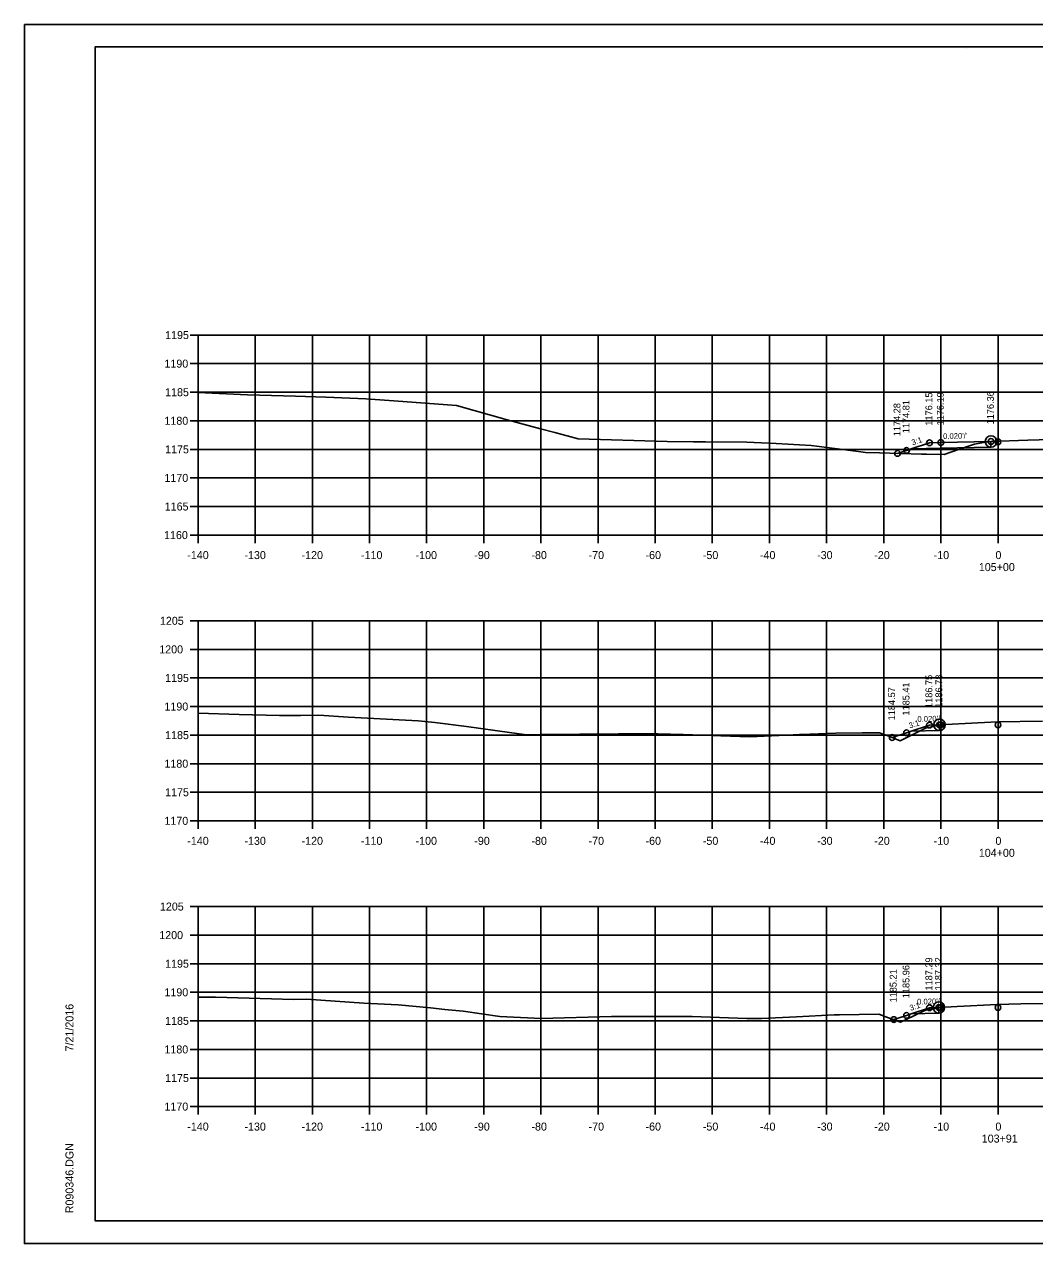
# Model space of a CAD drawing. Extents: x 1368971 to 1374497, y 378717 to 381839.
# Drawn here: x 1371092.2 to 1371269, y 380772.8 to 380986.1 of the extents above; entities that cross this region are included whole.
import ezdxf

# ---------------------------------------------------------------- set-up
doc = ezdxf.new("R2010")
doc.units = 0
for name, color, linetype in [('R_Alt Surface', 7, 'Continuous'), ('R_Axis', 7, 'Continuous'), ('R_Axis Annot', 7, 'Continuous'), ('R_Exist Surface', 7, 'Continuous'), ('R_Fin Surface', 7, 'Continuous'), ('R_Grid', 7, 'Continuous'), ('R_No Plot', 7, 'Continuous'), ('R_Xsect Elev', 7, 'Continuous'), ('R_Xsect Slope', 7, 'Continuous')]:
    doc.layers.add(name, color=color, linetype=linetype)

msp = doc.modelspace()

# ---------------------------------------------------------------- linework, layer by layer
at = {"layer": 'R_Alt Surface'}
for points in [[(1371261.41, 380913.1), (1371261.41, 380912.1), (1371252.64, 380911.92), (1371247.45, 380911.82)], [(1371252.39, 380863.52), (1371252.39, 380862.52), (1371247.45, 380862.42)], [(1371252.3, 380814.06), (1371252.3, 380813.06), (1371247.45, 380812.96)]]:
    msp.add_lwpolyline(points, dxfattribs=at)
at = {"layer": 'R_Axis'}
for p, q in [((1371121.24, 380931.73), (1371122.64, 380931.73)), ((1371122.64, 380896.73), (1371122.64, 380931.73)), ((1371121.24, 380926.73), (1371122.64, 380926.73)), ((1371121.24, 380921.73), (1371122.64, 380921.73)), ((1371121.24, 380916.73), (1371122.64, 380916.73)), ((1371121.24, 380911.73), (1371122.64, 380911.73)), ((1371121.24, 380906.73), (1371122.64, 380906.73)), ((1371121.24, 380901.73), (1371122.64, 380901.73)), ((1371121.24, 380896.73), (1371122.64, 380896.73)), ((1371122.64, 380896.73), (1371402.64, 380896.73)), ((1371122.64, 380895.33), (1371122.64, 380896.73)), ((1371132.64, 380895.33), (1371132.64, 380896.73)), ((1371142.64, 380895.33), (1371142.64, 380896.73)), ((1371152.64, 380895.33), (1371152.64, 380896.73)), ((1371162.64, 380895.33), (1371162.64, 380896.73)), ((1371172.64, 380895.33), (1371172.64, 380896.73)), ((1371182.64, 380895.33), (1371182.64, 380896.73)), ((1371192.64, 380895.33), (1371192.64, 380896.73)), ((1371202.64, 380895.33), (1371202.64, 380896.73)), ((1371212.64, 380895.33), (1371212.64, 380896.73)), ((1371222.64, 380895.33), (1371222.64, 380896.73)), ((1371232.64, 380895.33), (1371232.64, 380896.73)), ((1371242.64, 380895.33), (1371242.64, 380896.73)), ((1371252.64, 380895.33), (1371252.64, 380896.73)), ((1371262.64, 380895.33), (1371262.64, 380896.73)), ((1371121.24, 380881.73), (1371122.64, 380881.73)), ((1371122.64, 380846.73), (1371122.64, 380881.73)), ((1371121.24, 380876.73), (1371122.64, 380876.73)), ((1371121.24, 380871.73), (1371122.64, 380871.73)), ((1371121.24, 380866.73), (1371122.64, 380866.73)), ((1371121.24, 380861.73), (1371122.64, 380861.73)), ((1371121.24, 380856.73), (1371122.64, 380856.73)), ((1371121.24, 380851.73), (1371122.64, 380851.73)), ((1371121.24, 380846.73), (1371122.64, 380846.73)), ((1371122.64, 380846.73), (1371402.64, 380846.73)), ((1371122.64, 380845.33), (1371122.64, 380846.73)), ((1371132.64, 380845.33), (1371132.64, 380846.73)), ((1371142.64, 380845.33), (1371142.64, 380846.73)), ((1371152.64, 380845.33), (1371152.64, 380846.73)), ((1371162.64, 380845.33), (1371162.64, 380846.73)), ((1371172.64, 380845.33), (1371172.64, 380846.73)), ((1371182.64, 380845.33), (1371182.64, 380846.73)), ((1371192.64, 380845.33), (1371192.64, 380846.73)), ((1371202.64, 380845.33), (1371202.64, 380846.73)), ((1371212.64, 380845.33), (1371212.64, 380846.73)), ((1371222.64, 380845.33), (1371222.64, 380846.73)), ((1371232.64, 380845.33), (1371232.64, 380846.73)), ((1371242.64, 380845.33), (1371242.64, 380846.73)), ((1371252.64, 380845.33), (1371252.64, 380846.73)), ((1371262.64, 380845.33), (1371262.64, 380846.73)), ((1371121.24, 380831.73), (1371122.64, 380831.73)), ((1371122.64, 380796.73), (1371122.64, 380831.73)), ((1371121.24, 380826.73), (1371122.64, 380826.73)), ((1371121.24, 380821.73), (1371122.64, 380821.73)), ((1371121.24, 380816.73), (1371122.64, 380816.73)), ((1371121.24, 380811.73), (1371122.64, 380811.73)), ((1371121.24, 380806.73), (1371122.64, 380806.73)), ((1371121.24, 380801.73), (1371122.64, 380801.73)), ((1371121.24, 380796.73), (1371122.64, 380796.73)), ((1371122.64, 380796.73), (1371402.64, 380796.73)), ((1371122.64, 380795.33), (1371122.64, 380796.73)), ((1371132.64, 380795.33), (1371132.64, 380796.73)), ((1371142.64, 380795.33), (1371142.64, 380796.73)), ((1371152.64, 380795.33), (1371152.64, 380796.73)), ((1371162.64, 380795.33), (1371162.64, 380796.73)), ((1371172.64, 380795.33), (1371172.64, 380796.73)), ((1371182.64, 380795.33), (1371182.64, 380796.73)), ((1371192.64, 380795.33), (1371192.64, 380796.73)), ((1371202.64, 380795.33), (1371202.64, 380796.73)), ((1371212.64, 380795.33), (1371212.64, 380796.73)), ((1371222.64, 380795.33), (1371222.64, 380796.73)), ((1371232.64, 380795.33), (1371232.64, 380796.73)), ((1371242.64, 380795.33), (1371242.64, 380796.73)), ((1371252.64, 380795.33), (1371252.64, 380796.73)), ((1371262.64, 380795.33), (1371262.64, 380796.73))]:
    msp.add_line(p, q, dxfattribs=at)
at = {"layer": 'R_Exist Surface'}
for points in [[(1371122.64, 380921.69), (1371131.3, 380921.28), (1371139.66, 380921.01), (1371145.02, 380920.88), (1371152.02, 380920.59), (1371156.92, 380920.2), (1371167.89, 380919.41), (1371176.72, 380916.9), (1371182.58, 380915.31), (1371185.08, 380914.68), (1371189.17, 380913.59), (1371204.71, 380913.09), (1371209.36, 380913.02), (1371211.44, 380913.04), (1371218.7, 380912.97), (1371223.8, 380912.74), (1371229.91, 380912.38), (1371238.24, 380911.34), (1371239.46, 380911.17), (1371241.87, 380911.1), (1371249.23, 380910.91), (1371250.15, 380910.87), (1371253.22, 380910.81), (1371255.73, 380911.72), (1371258.5, 380912.62), (1371260.09, 380912.91), (1371261.41, 380913.1), (1371267.83, 380913.34), (1371271.83, 380913.48)], [(1371122.64, 380865.56), (1371129.84, 380865.35), (1371136.91, 380865.14), (1371140.56, 380865.14), (1371143.77, 380865.2), (1371148.96, 380864.85), (1371161.16, 380864.25), (1371164.1, 380863.95), (1371169.6, 380863.25), (1371177.16, 380862.19), (1371179.68, 380861.84), (1371180.8, 380861.78), (1371182.65, 380861.84), (1371196.24, 380861.93), (1371203.11, 380861.93), (1371207.52, 380861.85), (1371217.45, 380861.48), (1371219.21, 380861.42), (1371226.8, 380861.78), (1371227.88, 380861.83), (1371228.17, 380861.85), (1371234.27, 380862.07), (1371238.86, 380862.1), (1371241.9, 380862.14), (1371243.71, 380861.47), (1371245.53, 380860.75), (1371248.9, 380862.42), (1371249.96, 380862.93), (1371250.75, 380863.1), (1371252.39, 380863.52), (1371259.08, 380863.88), (1371262.54, 380864.06), (1371270.4, 380864.17)], [(1371122.64, 380815.89), (1371125.7, 380815.86), (1371135.46, 380815.57), (1371139.26, 380815.49), (1371141.6, 380815.53), (1371151.66, 380814.85), (1371157.65, 380814.56), (1371163.29, 380813.98), (1371165.82, 380813.72), (1371169.05, 380813.4), (1371175.42, 380812.51), (1371182.69, 380812.13), (1371195.02, 380812.52), (1371195.1, 380812.52), (1371195.24, 380812.52), (1371206.59, 380812.48), (1371209.13, 380812.5), (1371218.7, 380812.14), (1371221.23, 380812.16), (1371227.39, 380812.43), (1371233.96, 380812.79), (1371234.48, 380812.81), (1371234.87, 380812.81), (1371241.8, 380812.91), (1371243.95, 380812.11), (1371245.57, 380811.52), (1371246.42, 380811.91), (1371249.84, 380813.56), (1371251.34, 380813.89), (1371252.3, 380814.06), (1371255.48, 380814.24), (1371262.41, 380814.62), (1371266.62, 380814.68), (1371273.43, 380814.78)]]:
    msp.add_lwpolyline(points, dxfattribs=at)
at = {"layer": 'R_Fin Surface'}
for points in [[(1371245.06, 380911.02), (1371246.64, 380911.55), (1371247.45, 380911.82), (1371250.64, 380912.88), (1371252.64, 380912.92), (1371261.41, 380913.1)], [(1371244.12, 380861.31), (1371246.64, 380862.15), (1371247.45, 380862.42), (1371250.64, 380863.48), (1371252.39, 380863.52)], [(1371244.4, 380811.95), (1371246.64, 380812.69), (1371246.64, 380812.69), (1371246.65, 380812.69), (1371247.45, 380812.96), (1371247.46, 380812.97), (1371250.64, 380814.03), (1371250.65, 380814.03), (1371252.3, 380814.06), (1371252.3, 380814.06)]]:
    msp.add_lwpolyline(points, dxfattribs=at)
at = {"layer": 'R_Grid'}
for p, q in [((1371122.64, 380931.73), (1371402.64, 380931.73)), ((1371122.64, 380896.73), (1371122.64, 380931.73)), ((1371132.64, 380896.73), (1371132.64, 380931.73)), ((1371142.64, 380896.73), (1371142.64, 380931.73)), ((1371152.64, 380896.73), (1371152.64, 380931.73)), ((1371162.64, 380896.73), (1371162.64, 380931.73)), ((1371172.64, 380896.73), (1371172.64, 380931.73)), ((1371182.64, 380896.73), (1371182.64, 380931.73)), ((1371192.64, 380896.73), (1371192.64, 380931.73)), ((1371202.64, 380896.73), (1371202.64, 380931.73)), ((1371212.64, 380896.73), (1371212.64, 380931.73)), ((1371222.64, 380896.73), (1371222.64, 380931.73)), ((1371232.64, 380896.73), (1371232.64, 380931.73)), ((1371242.64, 380896.73), (1371242.64, 380931.73)), ((1371252.64, 380896.73), (1371252.64, 380931.73)), ((1371262.64, 380896.73), (1371262.64, 380931.73)), ((1371122.64, 380926.73), (1371402.64, 380926.73)), ((1371122.64, 380921.73), (1371402.64, 380921.73)), ((1371122.64, 380916.73), (1371402.64, 380916.73)), ((1371122.64, 380911.73), (1371402.64, 380911.73)), ((1371122.64, 380906.73), (1371402.64, 380906.73)), ((1371122.64, 380901.73), (1371402.64, 380901.73)), ((1371122.64, 380896.73), (1371402.64, 380896.73)), ((1371122.64, 380881.73), (1371402.64, 380881.73)), ((1371122.64, 380846.73), (1371122.64, 380881.73)), ((1371132.64, 380846.73), (1371132.64, 380881.73)), ((1371142.64, 380846.73), (1371142.64, 380881.73)), ((1371152.64, 380846.73), (1371152.64, 380881.73)), ((1371162.64, 380846.73), (1371162.64, 380881.73)), ((1371172.64, 380846.73), (1371172.64, 380881.73)), ((1371182.64, 380846.73), (1371182.64, 380881.73)), ((1371192.64, 380846.73), (1371192.64, 380881.73)), ((1371202.64, 380846.73), (1371202.64, 380881.73)), ((1371212.64, 380846.73), (1371212.64, 380881.73)), ((1371222.64, 380846.73), (1371222.64, 380881.73)), ((1371232.64, 380846.73), (1371232.64, 380881.73)), ((1371242.64, 380846.73), (1371242.64, 380881.73)), ((1371252.64, 380846.73), (1371252.64, 380881.73)), ((1371262.64, 380846.73), (1371262.64, 380881.73)), ((1371122.64, 380876.73), (1371402.64, 380876.73)), ((1371122.64, 380871.73), (1371402.64, 380871.73)), ((1371122.64, 380866.73), (1371402.64, 380866.73)), ((1371122.64, 380861.73), (1371402.64, 380861.73)), ((1371122.64, 380856.73), (1371402.64, 380856.73)), ((1371122.64, 380851.73), (1371402.64, 380851.73)), ((1371122.64, 380846.73), (1371402.64, 380846.73)), ((1371122.64, 380831.73), (1371402.64, 380831.73)), ((1371122.64, 380796.73), (1371122.64, 380831.73)), ((1371132.64, 380796.73), (1371132.64, 380831.73)), ((1371142.64, 380796.73), (1371142.64, 380831.73)), ((1371152.64, 380796.73), (1371152.64, 380831.73)), ((1371162.64, 380796.73), (1371162.64, 380831.73)), ((1371172.64, 380796.73), (1371172.64, 380831.73)), ((1371182.64, 380796.73), (1371182.64, 380831.73)), ((1371192.64, 380796.73), (1371192.64, 380831.73)), ((1371202.64, 380796.73), (1371202.64, 380831.73)), ((1371212.64, 380796.73), (1371212.64, 380831.73)), ((1371222.64, 380796.73), (1371222.64, 380831.73)), ((1371232.64, 380796.73), (1371232.64, 380831.73)), ((1371242.64, 380796.73), (1371242.64, 380831.73)), ((1371252.64, 380796.73), (1371252.64, 380831.73)), ((1371262.64, 380796.73), (1371262.64, 380831.73)), ((1371122.64, 380826.73), (1371402.64, 380826.73)), ((1371122.64, 380821.73), (1371402.64, 380821.73)), ((1371122.64, 380816.73), (1371402.64, 380816.73)), ((1371122.64, 380811.73), (1371402.64, 380811.73)), ((1371122.64, 380806.73), (1371402.64, 380806.73)), ((1371122.64, 380801.73), (1371402.64, 380801.73)), ((1371122.64, 380796.73), (1371402.64, 380796.73))]:
    msp.add_line(p, q, dxfattribs=at)
at = {"layer": 'R_No Plot'}
for p, q in [((1371092.24, 380986.09), (1371425.58, 380986.09)), ((1371104.64, 380982.19), (1371420.82, 380982.19)), ((1371104.64, 380776.73), (1371104.64, 380982.19)), ((1371257.16, 380981.93), (1371257.16, 380981.93)), ((1371257.16, 380981.93), (1371257.16, 380981.93)), ((1371104.64, 380776.73), (1371104.64, 380776.73)), ((1371420.82, 380776.73), (1371104.64, 380776.73)), ((1371092.24, 380772.76), (1371425.58, 380772.76))]:
    msp.add_line(p, q, dxfattribs=at)
for points in [[(1371092.24, 380986.09), (1371425.58, 380986.09), (1371425.58, 380772.75), (1371092.24, 380772.75)], [(1371338.56, 380982.19), (1371338.56, 380972.31), (1371374.3, 380972.31), (1371374.3, 380969.39), (1371397.49, 380969.39), (1371397.49, 380946.18), (1371420.82, 380946.18), (1371420.82, 380776.73), (1371104.64, 380776.73), (1371104.64, 380982.19)]]:
    msp.add_lwpolyline(points, close=True, dxfattribs=at)
for centre, radius in [((1371250.64, 380912.88), 0.5), ((1371252.64, 380912.92), 0.5), ((1371261.41, 380913.1), 1), ((1371261.41, 380913.1), 0.5), ((1371262.64, 380913.04), 0.5), ((1371245.06, 380911.02), 0.5), ((1371246.64, 380911.55), 0.5), ((1371250.64, 380863.48), 0.5), ((1371252.39, 380863.52), 1), ((1371252.39, 380863.52), 0.5), ((1371252.64, 380863.52), 0.5), ((1371262.64, 380863.52), 0.5), ((1371244.12, 380861.31), 0.5), ((1371246.64, 380862.15), 0.5), ((1371250.64, 380814.03), 0.5), ((1371252.3, 380814.06), 1), ((1371252.3, 380814.06), 0.5), ((1371252.64, 380814.07), 0.5), ((1371262.64, 380814.07), 0.5), ((1371244.4, 380811.95), 0.5), ((1371246.64, 380812.69), 0.5)]:
    msp.add_circle(centre, radius, dxfattribs=at)

# ---------------------------------------------------------------- texts
at = {"layer": 'R_Axis'}
for p in [(1371122.64, 380896.73), (1371122.64, 380846.73), (1371122.64, 380796.73)]:
    msp.add_text('-', height=0.0001, dxfattribs=at).set_placement(p)
at = {"layer": 'R_Axis Annot'}
for s, p in [('1195', (1371116.87, 380931.03)), ('1190', (1371116.75, 380926.03)), ('1185', (1371116.87, 380921.03)), ('1180', (1371116.75, 380916.03)), ('1175', (1371116.87, 380911.03)), ('1170', (1371116.75, 380906.03)), ('1165', (1371116.8, 380901.03)), ('1160', (1371116.68, 380896.03)), ('-140', (1371120.75, 380892.53)), ('-130', (1371130.75, 380892.53)), ('-120', (1371140.75, 380892.53)), ('-110', (1371151.15, 380892.53)), ('-100', (1371160.7, 380892.53)), ('-90', (1371170.98, 380892.53)), ('-80', (1371180.98, 380892.53)), ('-70', (1371190.98, 380892.53)), ('-60', (1371200.95, 380892.53)), ('-50', (1371210.98, 380892.53)), ('-40', (1371220.98, 380892.53)), ('-30', (1371230.98, 380892.53)), ('-20', (1371240.98, 380892.53)), ('-10', (1371251.38, 380892.53)), ('0', (1371262.19, 380892.53)), ('105+00', (1371259.28, 380890.43)), ('1205', (1371115.96, 380881.03)), ('1200', (1371115.84, 380876.03)), ('1195', (1371116.87, 380871.03)), ('1190', (1371116.75, 380866.03)), ('1185', (1371116.87, 380861.03)), ('1180', (1371116.75, 380856.03)), ('1175', (1371116.87, 380851.03)), ('1170', (1371116.75, 380846.03)), ('-140', (1371120.75, 380842.53)), ('-130', (1371130.75, 380842.53)), ('-120', (1371140.75, 380842.53)), ('-110', (1371151.15, 380842.53)), ('-100', (1371160.7, 380842.53)), ('-90', (1371170.98, 380842.53)), ('-80', (1371180.98, 380842.53)), ('-70', (1371190.98, 380842.53)), ('-60', (1371200.95, 380842.53)), ('-50', (1371210.98, 380842.53)), ('-40', (1371220.98, 380842.53)), ('-30', (1371230.98, 380842.53)), ('-20', (1371240.98, 380842.53)), ('-10', (1371251.38, 380842.53)), ('0', (1371262.19, 380842.53)), ('104+00', (1371259.28, 380840.43)), ('1205', (1371115.96, 380831.03)), ('1200', (1371115.84, 380826.03)), ('1195', (1371116.87, 380821.03)), ('1190', (1371116.75, 380816.03)), ('1185', (1371116.87, 380811.03)), ('1180', (1371116.75, 380806.03)), ('1175', (1371116.87, 380801.03)), ('1170', (1371116.75, 380796.03)), ('-140', (1371120.75, 380792.53)), ('-130', (1371130.75, 380792.53)), ('-120', (1371140.75, 380792.53)), ('-110', (1371151.15, 380792.53)), ('-100', (1371160.7, 380792.53)), ('-90', (1371170.98, 380792.53)), ('-80', (1371180.98, 380792.53)), ('-70', (1371190.98, 380792.53)), ('-60', (1371200.95, 380792.53)), ('-50', (1371210.98, 380792.53)), ('-40', (1371220.98, 380792.53)), ('-30', (1371230.98, 380792.53)), ('-20', (1371240.98, 380792.53)), ('-10', (1371251.38, 380792.53)), ('0', (1371262.19, 380792.53)), ('103+91', (1371259.79, 380790.43))]:
    msp.add_text(s, height=1.4, dxfattribs=at).set_placement(p)
at = {"layer": 'R_No Plot'}
for s, p in [('7/21/2016', (1371100.83, 380806.38)), ('R090346.DGN', (1371100.83, 380778.06))]:
    msp.add_text(s, height=1.4, rotation=90, dxfattribs=at).set_placement(p)
at = {"layer": 'R_Xsect Elev'}
for s, p in [('1176.15', (1371251.14, 380915.88)), ('1176.19', (1371253.14, 380915.92)), ('1176.36', (1371261.91, 380916.1)), ('1176.36', (1371261.91, 380916.1)), ('1174.28', (1371245.56, 380914.02)), ('1174.81', (1371247.14, 380914.55)), ('1186.75', (1371251.14, 380866.48)), ('1186.78', (1371252.89, 380866.52)), ('1184.57', (1371244.62, 380864.31)), ('1185.41', (1371247.14, 380865.15)), ('1187.29', (1371251.14, 380817.03)), ('1187.32', (1371252.8, 380817.06)), ('1185.21', (1371244.9, 380814.95)), ('1185.96', (1371247.14, 380815.69))]:
    msp.add_text(s, height=1.2, rotation=90, dxfattribs=at).set_placement(p)
at = {"layer": 'R_Xsect Slope'}
for s, rotation, p in [("0.020'/'", 1.1458, (1371253.04, 380913.53)), ('3:1', 18.4337, (1371247.69, 380912.42)), ('3:1', 18.4339, (1371247.22, 380862.87)), ("0.020'/'", 1.1458, (1371248.54, 380864.04)), ('3:1', 18.4338, (1371247.36, 380813.46)), ("0.020'/'", 1.1458, (1371248.49, 380814.58))]:
    msp.add_text(s, height=1, rotation=rotation, dxfattribs=at).set_placement(p)

doc.saveas('drawing.dxf')
